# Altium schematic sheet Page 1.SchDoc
size 431 x 279 mm; Date: Not shown in title block; ApprovedBy: Not shown in title block; CheckedBy: Not shown in title block; Author: Not shown in title block; CompanyName: Not shown in title block; Engineer: Not shown in title block; Organization: Not shown in title block; Address1: Not shown in title block; Address2: Not shown in title block; Address3: Not shown in title block; Address4: Not shown in title block; DocumentNumber: 1; Revision: Use project parameter SCH_Rev; SheetNumber: 2; SheetTotal: 3; PageSetup: Record=PageOptions¦CenterHorizontal=True¦CenterVertical=True¦PrintScale=1.00¦XCorrection=1.00¦YCorrection=1.00¦PrintKind=0¦BorderSize=5000000¦LeftOffset=0¦BottomOffset=0¦Orientation=2¦PaperLength=2794¦PaperWidth=2159¦Scale=100¦PaperSource=1¦PrintQuality=600¦MediaType=1¦DitherType=10¦PrintScaleMode=1¦PaperKind=Letter¦PaperIndex=1
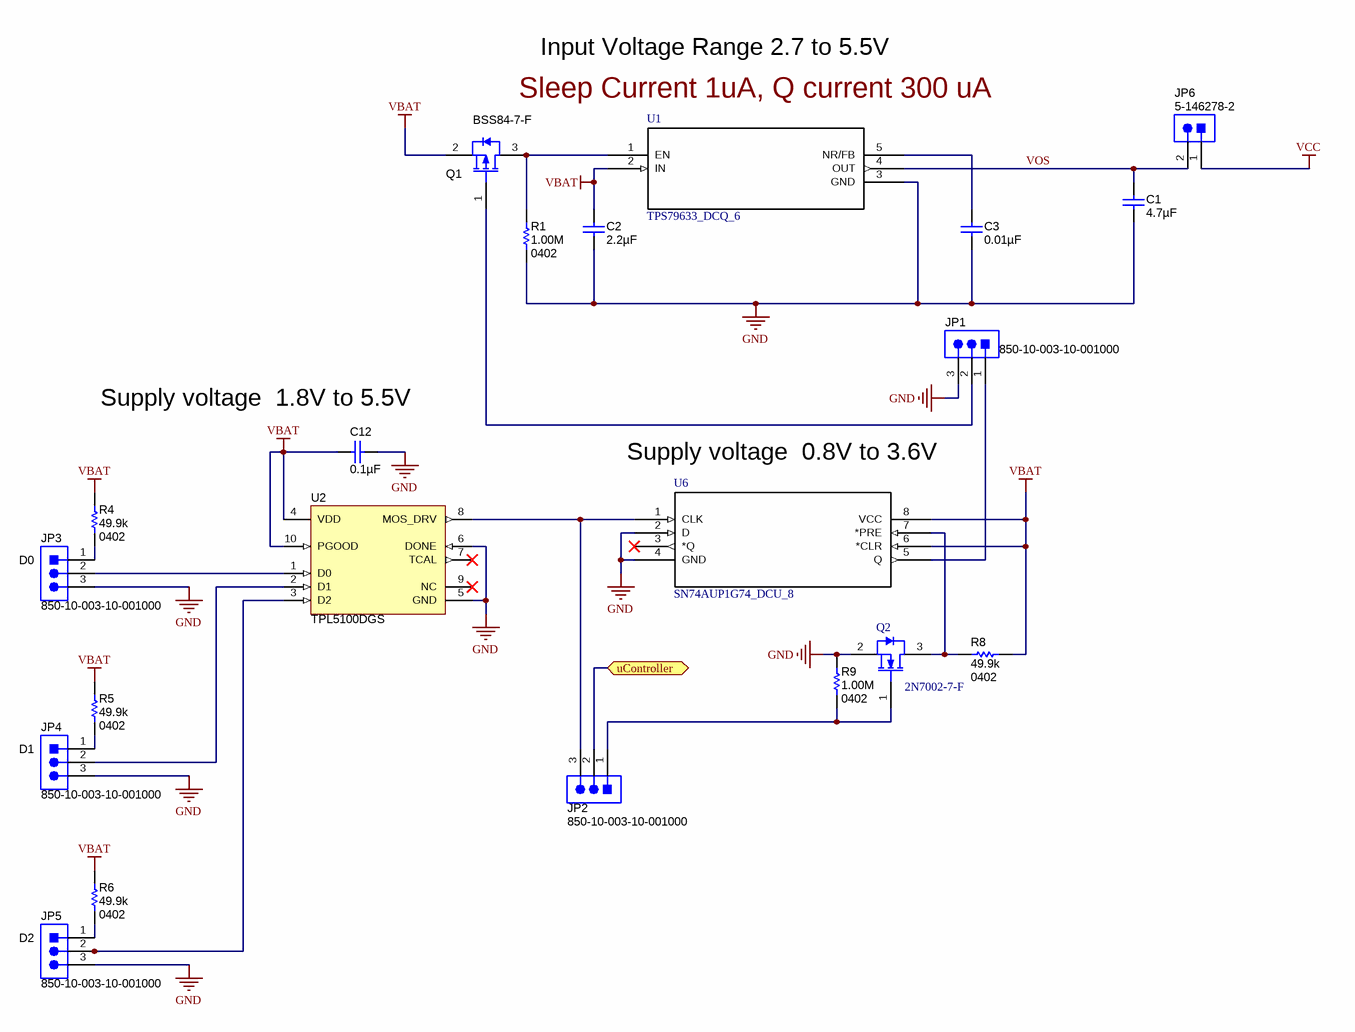
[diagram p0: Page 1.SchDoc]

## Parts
C1  ValueDisplayed: 4.7µF  [0402]  (hidden comment: C1005X5R0J475M050BC)
C2  ValueDisplayed: 2.2µF  [0603]  (hidden comment: GRM188C80J225KE19D)
C3  ValueDisplayed: 0.01µF  [0402]  (hidden comment: GRM155R61A103KA01D)
C12  ValueDisplayed: 0.1µF  [0402L]  (hidden comment: GRM155R71A104KA01D)
JP1  850-10-003-10-001000  [Mill-Max_850-10-003-10-001000]
JP2  850-10-003-10-001000  [Mill-Max_850-10-003-10-001000]
JP3  850-10-003-10-001000  [Mill-Max_850-10-003-10-001000]
JP4  850-10-003-10-001000  [Mill-Max_850-10-003-10-001000]
JP5  850-10-003-10-001000  [Mill-Max_850-10-003-10-001000]
JP6  5-146278-2  [TE_5-146278-2]
Q1  BSS84-7-F  [SOT-23]
Q2  2N7002-7-F  [SOT-23]
R1  ValueDisplayed: 1.00M  PackageReference: 0402  [0402L]  (hidden comment: CRCW04021M00FKED)
R4  value 49.9k  PackageReference: 0402  [0402L]  (hidden comment: CRCW040249K9FKED)
R5  value 49.9k  PackageReference: 0402  [0402L]  (hidden comment: CRCW040249K9FKED)
R6  value 49.9k  PackageReference: 0402  [0402L]  (hidden comment: CRCW040249K9FKED)
R8  value 49.9k  PackageReference: 0402  [0402L]  (hidden comment: CRCW040249K9FKED)
R9  ValueDisplayed: 1.00M  PackageReference: 0402  [0402L]  (hidden comment: CRCW04021M00FKED)
U1  TPS79633_DCQ_6  [DCQ6]
U2  TPL5100DGS  [DGS0010A_N]
U6  SN74AUP1G74_DCU_8  [DCU8]

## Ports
uController (bidir)

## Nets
GND: C1.2 C2.2 C3.2 C12.2 JP1.3 JP3.3 JP4.3 JP5.3 Q2.2(S) R1.1 R9.2 U1.3(GND) U2.5(GND) U2.6(DONE) U6.2(D) U6.4(GND)
VBAT: C2.1 C12.1 Q1.2(S) R4.2 R5.2 R6.2 R8.2 U1.2(IN) U2.4(VDD) U2.10(PGOOD) U6.6(*CLR) U6.8(VCC)
VCC: JP6.1
uController: JP2.2 ; port uController
VOS: C1.1 JP6.2 U1.4(OUT)
NetC3_1: C3.1 U1.5(NR/FB)
NetJP1_1: JP1.1 U6.5(Q)
NetJP1_2: JP1.2 Q1.1(G)
NetJP2_1: JP2.1 Q2.1(G) R9.1
NetJP2_3: JP2.3 U2.8(MOS_DRV) U6.1(CLK)
NetJP3_1: JP3.1 R4.1
NetJP3_2: JP3.2 U2.1(D0)
NetJP4_1: JP4.1 R5.1
NetJP4_2: JP4.2 U2.2(D1)
NetJP5_1: JP5.1 R6.1
NetJP5_2: JP5.2 U2.3(D2)
NetQ1_3: Q1.3(D) R1.2 U1.1(EN)
NetQ2_3: Q2.3(D) R8.1 U6.7(*PRE)

Not connected (* = marked no-connect by the designer): U2 7(TCAL)* 9(NC)*; U6 3(*Q)*

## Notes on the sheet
- Input Voltage Range 2.7 to 5.5V
- Sleep Current 1uA, Q current 300 uA
- (near C12) Supply voltage  1.8V to 5.5V
- Supply voltage  0.8V to 3.6V
- (near JP3) D0
- (near JP4) D1
- (near JP5) D2

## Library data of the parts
C1 = C1005X5R0J475M050BC: CAP, CERM, 4.7uF, 6.3V, +/-20%, X5R, 0402; Manufacturer: TDK; Polarized: N; CompType: Capacitor; U/M: EA; Cap_F: 0.0000047; Tolerance_%: 20; Value1: Unknown; VDC_V: 6.3; TaMin_C: -55; TaMax_C: 85
C2 = GRM188C80J225KE19D: CAP, CERM, 2.2 µF, 6.3 V, +/- 10%, X6S, 0603; Manufacturer: MuRata; Polarized: N; CompType: Capacitor; Value: 2.2uF; U/M: EA; Cap_F: 0.0000022; Tolerance_%: 10; Value1: Unknown; VDC_V: 6.3; Value2: 6.3V; TaMin_C: -55; TaMax_C: 105
C3 = GRM155R61A103KA01D: CAP, CERM, 0.01uF, 10V, +/-10%, X5R, 0402; Manufacturer: MuRata; Polarized: N; CompType: Capacitor; U/M: EA; Cap_F: 0.00000001; Tolerance_%: 10; Value1: Unknown; TaMin_C: -55; TaMax_C: 85
C12 = GRM155R71A104KA01D: CAP, CERM, 0.1uF, 10V, +/-10%, X7R, 0402; Manufacturer: MuRata; Polarized: N; CompType: Capacitor; U/M: EA; Cap_F: 0.0000001; Tolerance_%: 10; Value1: Unknown; TaMin_C: -55; TaMax_C: 125; Cap_Case: 0402
JP1-JP5 = 850-10-003-10-001000: Header, 50mil, 3x1, Gold, TH; Manufacturer: Mill-Max; SymbolCreator: a0799628; U/M: EA
JP6 = 5-146278-2: Header, 100mil, 2x1, Tin, TH; Manufacturer: TE Connectivity; SymbolCreator: a0412235; U/M: EA
Q1 = BSS84-7-F: MOSFET, P-CH, -50V, -0.13A, SOT-23; Manufacturer: Diodes Inc.; Alternate Manufacturer: None; U/M: EA; ChType: P; VdsMax_V: -50; Value1: ? ohm; Value2: ? nC; Vgs_V: 20; IdsMax_A: -0.13
Q2 = 2N7002-7-F: MOSFET, N-CH, 60 V, 0.17 A, SOT-23; Manufacturer: Diodes Inc.; Alternate Manufacturer: None; U/M: EA; ChType: N; Value: 60V; VdsMax_V: 60; Value1: 7.5 ohm; Rdson45_ohm: 7.5; Value2: 223 nC; QgTyp_nC: 223; Vgs_V: 20; IdsMax_A: 0.17
R1 R9 = CRCW04021M00FKED: RES, 1.00 M, 1%, 0.063 W, 0402; Manufacturer: Vishay-Dale; CompType: Resistor; Res_ohm: 1000000; Value: 1.00Meg; Value_Code: 1M00; Tolerance_%: 1; Power_W: 0.063; Value2: 0.063W; VDC_V: 50; TempCo: 100 ppm/C; EIA_Code: E96; U/M: EA
R4-R6 R8 = CRCW040249K9FKED: RES, 49.9k ohm, 1%, 0.063W, 0402; Manufacturer: Vishay-Dale; CompType: Resistor; Res_ohm: 49900; Value_Code: 49k9; Tolerance_%: 1; Power_W: 0.063; VDC_V: 50; TempCo: 100 ppm/C; EIA_Code: E96; U/M: EA
U1 = TPS79633_DCQ_6: Imported; Vendor: Texas Instruments; PACKAGE_DESIGNATOR: DCQ; PIN_COUNT: 6; FAMILY_NAME: SINGLE CHANNEL LDO; INDUSTRY_STD_PKG_TYPE: SOT-223
U2 = TPL5100DGS: Nano Power Programmable Timer, DGS0010A; Alternate Manufacturer: None; Manufacturer: Texas Instruments; SymbolCreator: a0411947; CompType: IC; U/M: EA
U6 = SN74AUP1G74_DCU_: Imported; Manufacturer: Texas Instruments; PACKAGE_DESIGNATOR: DCU; PIN_COUNT: 8; FAMILY_NAME: LL FLIP-FLOP; INDUSTRY_STD_PKG_TYPE: US8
